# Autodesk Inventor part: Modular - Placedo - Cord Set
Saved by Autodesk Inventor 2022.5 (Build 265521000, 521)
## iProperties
Created: 2025-01
Part Number: Modular - Placedo - Cord Set
Material: Generic
Document SubType Name: Modeling
Designer: AdminForWorker
Density: 1 g/cm^3
Appearance: Default
Title: Modular - Placedo - Cord Set v4
Author: AdminForWorker
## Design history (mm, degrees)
feature "Body1"
feature "Body2"
feature "Body3"
body "Solid1"
body "Solid2"
body "Solid3"
